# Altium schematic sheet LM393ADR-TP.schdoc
size 127 x 101 mm
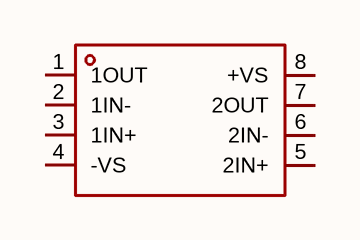
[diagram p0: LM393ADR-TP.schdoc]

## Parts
U?  lm393adr-tp  [SOIC-8_L4.9-W3.9-P1.27-LS6.0-BL]  (value not drawn)

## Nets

Not connected (* = marked no-connect by the designer): U? 1(1OUT) 2(1IN-) 3(1IN+) 4(-VS) 5(2IN+) 6(2IN-) 7(2OUT) 8(+VS)

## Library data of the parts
U? = lm393adr-tp: 比较器数:双路;输入失调电压(Vos):4mV;输入偏置电流(Ib):65nA;; Manufacturer: TECH PUBLIC(台舟); AddInBom: yes; ModelId: e81d2f7d937b4a6ab1dca543ff5d56a4; ModelName: SOIC-8_L4.9-W3.9-H1.7-LS6.0-P1.27; ModelTransform: 192.913,236.22,0,0,0,0,0,0,0; Number of Channels: 双路; Vos - Input Offset Voltage: 4mV; Ib - Input Bias Current: 65nA; Propagation Delay Time: 350ns; Output Mode: CMOS；TTL; Quiescent Current: 600uA; Maximum Power Supply Range (Vdd-Vss): 30V; Single Supply: 3V~30V; Dual Supply: -15V~-1.5V；1.5V~15V; Input Offset Current(Ios): 5nA; Response Time (tr): 1.4us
